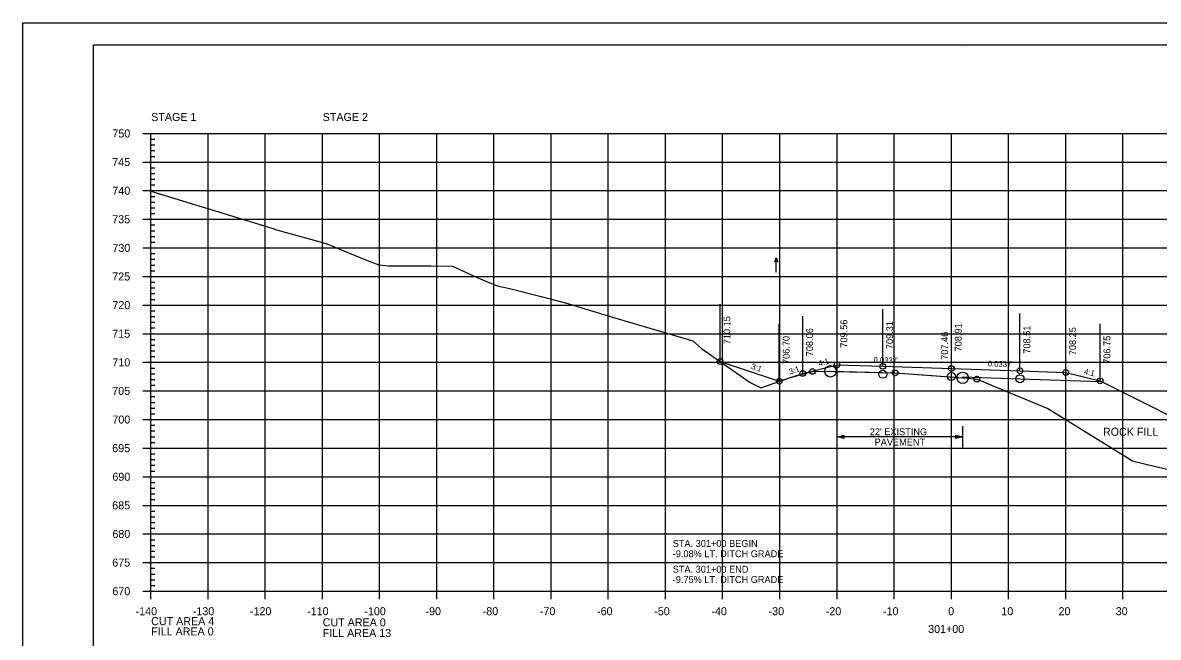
# Model space of a CAD drawing. Extents: x 1370515 to 1370849, y 383299 to 386073.
# Drawn here: x 1370515.4 to 1370714, y 383618.7 to 383726.1 of the extents above; entities that cross this region are included whole.
import ezdxf

# ---------------------------------------------------------------- set-up
doc = ezdxf.new("R2010")
doc.units = 0
for name, color, linetype in [('R_Alt Surface', 7, 'Continuous'), ('R_Axis', 7, 'Continuous'), ('R_Axis Annot', 7, 'Continuous'), ('R_Border', 7, 'Continuous'), ('R_Drive', 7, 'Continuous'), ('R_Exist Surface', 7, 'Continuous'), ('R_Fin Surface', 7, 'Continuous'), ('R_Grid', 7, 'Continuous'), ('R_No Plot', 7, 'Continuous'), ('R_ROW Annot', 7, 'Continuous'), ('R_Water Annot', 7, 'Continuous'), ('R_Xsect Elev', 7, 'Continuous'), ('R_Xsect Slope', 7, 'Continuous')]:
    doc.layers.add(name, color=color, linetype=linetype)

msp = doc.modelspace()

# ---------------------------------------------------------------- linework, layer by layer
at = {"layer": 'R_Alt Surface'}
msp.add_lwpolyline([(1370653.2, 383665.16), (1370656.65, 383665.18), (1370667.97, 383664.9), (1370679.78, 383664.05), (1370679.78, 383664.21), (1370689.8, 383663.88), (1370703.96, 383663.41)], dxfattribs=at)
at = {"layer": 'R_Axis'}
for p, q in [((1370536.4, 383706.75), (1370539.2, 383706.75)), ((1370537.8, 383626.75), (1370537.8, 383706.75)), ((1370537.8, 383705.75), (1370538.5, 383705.75)), ((1370537.8, 383704.75), (1370538.5, 383704.75)), ((1370537.8, 383703.75), (1370538.5, 383703.75)), ((1370536.4, 383701.75), (1370539.2, 383701.75)), ((1370537.8, 383702.75), (1370538.5, 383702.75)), ((1370537.8, 383700.75), (1370538.5, 383700.75)), ((1370537.8, 383699.75), (1370538.5, 383699.75)), ((1370537.8, 383698.75), (1370538.5, 383698.75)), ((1370537.8, 383697.75), (1370538.5, 383697.75)), ((1370536.4, 383696.75), (1370539.2, 383696.75)), ((1370537.8, 383695.75), (1370538.5, 383695.75)), ((1370537.8, 383694.75), (1370538.5, 383694.75)), ((1370537.8, 383693.75), (1370538.5, 383693.75)), ((1370536.4, 383691.75), (1370539.2, 383691.75)), ((1370537.8, 383692.75), (1370538.5, 383692.75)), ((1370537.8, 383690.75), (1370538.5, 383690.75)), ((1370537.8, 383689.75), (1370538.5, 383689.75)), ((1370537.8, 383688.75), (1370538.5, 383688.75)), ((1370537.8, 383687.75), (1370538.5, 383687.75)), ((1370536.4, 383686.75), (1370539.2, 383686.75)), ((1370537.8, 383685.75), (1370538.5, 383685.75)), ((1370537.8, 383684.75), (1370538.5, 383684.75)), ((1370537.8, 383683.75), (1370538.5, 383683.75)), ((1370536.4, 383681.75), (1370539.2, 383681.75)), ((1370537.8, 383682.75), (1370538.5, 383682.75)), ((1370537.8, 383680.75), (1370538.5, 383680.75)), ((1370537.8, 383679.75), (1370538.5, 383679.75)), ((1370537.8, 383678.75), (1370538.5, 383678.75)), ((1370537.8, 383677.75), (1370538.5, 383677.75)), ((1370536.4, 383676.75), (1370539.2, 383676.75)), ((1370537.8, 383675.75), (1370538.5, 383675.75)), ((1370537.8, 383674.75), (1370538.5, 383674.75)), ((1370537.8, 383673.75), (1370538.5, 383673.75)), ((1370536.4, 383671.75), (1370539.2, 383671.75)), ((1370537.8, 383672.75), (1370538.5, 383672.75)), ((1370537.8, 383670.75), (1370538.5, 383670.75)), ((1370537.8, 383669.75), (1370538.5, 383669.75)), ((1370537.8, 383668.75), (1370538.5, 383668.75)), ((1370537.8, 383667.75), (1370538.5, 383667.75)), ((1370536.4, 383666.75), (1370539.2, 383666.75)), ((1370537.8, 383665.75), (1370538.5, 383665.75)), ((1370537.8, 383664.75), (1370538.5, 383664.75)), ((1370537.8, 383663.75), (1370538.5, 383663.75)), ((1370536.4, 383661.75), (1370539.2, 383661.75)), ((1370537.8, 383662.75), (1370538.5, 383662.75)), ((1370537.8, 383660.75), (1370538.5, 383660.75)), ((1370537.8, 383659.75), (1370538.5, 383659.75)), ((1370537.8, 383658.75), (1370538.5, 383658.75)), ((1370537.8, 383657.75), (1370538.5, 383657.75)), ((1370536.4, 383656.75), (1370539.2, 383656.75)), ((1370537.8, 383655.75), (1370538.5, 383655.75)), ((1370537.8, 383654.75), (1370538.5, 383654.75)), ((1370537.8, 383653.75), (1370538.5, 383653.75)), ((1370536.4, 383651.75), (1370539.2, 383651.75)), ((1370537.8, 383652.75), (1370538.5, 383652.75)), ((1370537.8, 383650.75), (1370538.5, 383650.75)), ((1370537.8, 383649.75), (1370538.5, 383649.75)), ((1370537.8, 383648.75), (1370538.5, 383648.75)), ((1370537.8, 383647.75), (1370538.5, 383647.75)), ((1370536.4, 383646.75), (1370539.2, 383646.75)), ((1370537.8, 383645.75), (1370538.5, 383645.75)), ((1370537.8, 383644.75), (1370538.5, 383644.75)), ((1370537.8, 383643.75), (1370538.5, 383643.75)), ((1370536.4, 383641.75), (1370539.2, 383641.75)), ((1370537.8, 383642.75), (1370538.5, 383642.75)), ((1370537.8, 383640.75), (1370538.5, 383640.75)), ((1370537.8, 383639.75), (1370538.5, 383639.75)), ((1370537.8, 383638.75), (1370538.5, 383638.75)), ((1370537.8, 383637.75), (1370538.5, 383637.75)), ((1370536.4, 383636.75), (1370539.2, 383636.75)), ((1370537.8, 383635.75), (1370538.5, 383635.75)), ((1370537.8, 383634.75), (1370538.5, 383634.75)), ((1370537.8, 383633.75), (1370538.5, 383633.75)), ((1370536.4, 383631.75), (1370539.2, 383631.75)), ((1370537.8, 383632.75), (1370538.5, 383632.75)), ((1370537.8, 383630.75), (1370538.5, 383630.75)), ((1370537.8, 383629.75), (1370538.5, 383629.75)), ((1370537.8, 383628.75), (1370538.5, 383628.75)), ((1370537.8, 383625.35), (1370537.8, 383628.15)), ((1370537.8, 383627.75), (1370538.5, 383627.75)), ((1370547.8, 383625.35), (1370547.8, 383628.15)), ((1370557.8, 383625.35), (1370557.8, 383628.15)), ((1370567.8, 383625.35), (1370567.8, 383628.15)), ((1370577.8, 383625.35), (1370577.8, 383628.15)), ((1370587.8, 383625.35), (1370587.8, 383628.15)), ((1370597.8, 383625.35), (1370597.8, 383628.15)), ((1370607.8, 383625.35), (1370607.8, 383628.15)), ((1370617.8, 383625.35), (1370617.8, 383628.15)), ((1370627.8, 383625.35), (1370627.8, 383628.15)), ((1370637.8, 383625.35), (1370637.8, 383628.15)), ((1370647.8, 383625.35), (1370647.8, 383628.15)), ((1370657.8, 383625.35), (1370657.8, 383628.15)), ((1370667.8, 383625.35), (1370667.8, 383628.15)), ((1370677.8, 383625.35), (1370677.8, 383628.15)), ((1370687.8, 383625.35), (1370687.8, 383628.15)), ((1370697.8, 383625.35), (1370697.8, 383628.15)), ((1370707.8, 383625.35), (1370707.8, 383628.15)), ((1370536.4, 383626.75), (1370539.2, 383626.75)), ((1370537.8, 383626.75), (1370817.8, 383626.75))]:
    msp.add_line(p, q, dxfattribs=at)
at = {"layer": 'R_Border'}
for p, q in [((1370527.8, 383722.21), (1370843.98, 383722.21)), ((1370527.8, 383516.75), (1370527.8, 383722.21)), ((1370680.32, 383721.95), (1370680.32, 383721.95)), ((1370680.32, 383721.95), (1370680.32, 383721.95))]:
    msp.add_line(p, q, dxfattribs=at)
at = {"layer": 'R_Exist Surface'}
msp.add_lwpolyline([(1370537.8, 383696.68), (1370559.38, 383690.06), (1370559.45, 383690.03), (1370559.79, 383689.93), (1370567.41, 383687.8), (1370568.57, 383687.48), (1370575.54, 383684.63), (1370577.66, 383683.77), (1370578.88, 383683.67), (1370579.39, 383683.62), (1370586.76, 383683.6), (1370590.58, 383683.55), (1370594.99, 383681.51), (1370598.39, 383680.09), (1370600.31, 383679.69), (1370606.05, 383678.23), (1370610.31, 383677.15), (1370618.56, 383674.66), (1370632.56, 383670.53), (1370634.12, 383669.14), (1370642.61, 383663.25), (1370644.47, 383662.29), (1370649.68, 383664.07), (1370650.39, 383664.28), (1370653.42, 383665.13), (1370653.51, 383665.16), (1370656.63, 383665.18), (1370656.65, 383665.18), (1370657.29, 383665.16), (1370667.97, 383664.9), (1370678.41, 383664.16), (1370679.78, 383664.05), (1370680.07, 383664.03), (1370682.27, 383663.82), (1370682.6, 383663.68), (1370684.1, 383663.04), (1370693.65, 383659.08), (1370694.69, 383658.65), (1370708.06, 383650.39), (1370709.49, 383649.54), (1370711.57, 383649.01), (1370723.09, 383646.26)], dxfattribs=at)
at = {"layer": 'R_Fin Surface'}
msp.add_lwpolyline([(1370637.35, 383666.9), (1370647.71, 383663.45), (1370651.8, 383664.81), (1370657.8, 383666.31), (1370665.8, 383666.05), (1370677.8, 383665.65), (1370689.8, 383665.26), (1370697.8, 383664.99), (1370703.8, 383663.49), (1370744.75, 383643.02), (1370751.75, 383643.02), (1370755.24, 383644.18)], dxfattribs=at)
at = {"layer": 'R_Grid'}
for p, q in [((1370537.8, 383706.75), (1370817.8, 383706.75)), ((1370537.8, 383626.75), (1370537.8, 383706.75)), ((1370547.8, 383626.75), (1370547.8, 383706.75)), ((1370557.8, 383626.75), (1370557.8, 383706.75)), ((1370567.8, 383626.75), (1370567.8, 383706.75)), ((1370577.8, 383626.75), (1370577.8, 383706.75)), ((1370587.8, 383626.75), (1370587.8, 383706.75)), ((1370597.8, 383626.75), (1370597.8, 383706.75)), ((1370607.8, 383626.75), (1370607.8, 383706.75)), ((1370617.8, 383626.75), (1370617.8, 383706.75)), ((1370627.8, 383626.75), (1370627.8, 383706.75)), ((1370637.8, 383626.75), (1370637.8, 383706.75)), ((1370647.8, 383626.75), (1370647.8, 383706.75)), ((1370657.8, 383626.75), (1370657.8, 383706.75)), ((1370667.8, 383626.75), (1370667.8, 383706.75)), ((1370677.8, 383626.75), (1370677.8, 383706.75)), ((1370687.8, 383626.75), (1370687.8, 383706.75)), ((1370697.8, 383626.75), (1370697.8, 383706.75)), ((1370707.8, 383626.75), (1370707.8, 383706.75)), ((1370537.8, 383701.75), (1370817.8, 383701.75)), ((1370537.8, 383696.75), (1370817.8, 383696.75)), ((1370537.8, 383691.75), (1370817.8, 383691.75)), ((1370537.8, 383686.75), (1370817.8, 383686.75)), ((1370537.8, 383681.75), (1370817.8, 383681.75)), ((1370537.8, 383676.75), (1370817.8, 383676.75)), ((1370537.8, 383671.75), (1370817.8, 383671.75)), ((1370537.8, 383666.75), (1370817.8, 383666.75)), ((1370537.8, 383661.75), (1370817.8, 383661.75)), ((1370537.8, 383656.75), (1370817.8, 383656.75)), ((1370537.8, 383651.75), (1370817.8, 383651.75)), ((1370537.8, 383646.75), (1370817.8, 383646.75)), ((1370537.8, 383641.75), (1370817.8, 383641.75)), ((1370537.8, 383636.75), (1370817.8, 383636.75)), ((1370537.8, 383631.75), (1370817.8, 383631.75)), ((1370537.8, 383626.75), (1370817.8, 383626.75))]:
    msp.add_line(p, q, dxfattribs=at)
at = {"layer": 'R_No Plot'}
msp.add_line((1370515.4, 383726.1), (1370848.73, 383726.1), dxfattribs=at)
for points in [[(1370515.39, 383726.1), (1370848.73, 383726.1), (1370848.73, 383512.76), (1370515.39, 383512.76)], [(1370761.72, 383722.21), (1370761.72, 383712.33), (1370797.45, 383712.33), (1370797.45, 383709.41), (1370820.65, 383709.41), (1370820.65, 383686.19), (1370843.98, 383686.19), (1370843.98, 383516.75), (1370527.8, 383516.75), (1370527.8, 383722.21)]]:
    msp.add_lwpolyline(points, close=True, dxfattribs=at)
for centre, radius in [((1370637.35, 383666.9), 0.5), ((1370653.51, 383665.16), 0.5), ((1370656.65, 383665.18), 1), ((1370657.8, 383666.31), 0.5), ((1370665.8, 383664.67), 0.7), ((1370665.8, 383666.05), 0.5), ((1370667.97, 383664.9), 0.5), ((1370677.8, 383665.65), 0.5), ((1370689.8, 383665.26), 0.5), ((1370697.8, 383664.99), 0.5), ((1370647.71, 383663.45), 0.5), ((1370651.8, 383664.81), 0.5), ((1370651.8, 383664.81), 0.5), ((1370677.8, 383664.28), 0.7), ((1370677.8, 383664.28), 0.7), ((1370679.78, 383664.05), 1), ((1370682.27, 383663.82), 0.5), ((1370689.8, 383663.88), 0.7), ((1370703.8, 383663.49), 0.5), ((1370703.8, 383663.49), 0.5)]:
    msp.add_circle(centre, radius, dxfattribs=at)
at = {"layer": 'R_ROW Annot'}
for p, q in [((1370657.8, 383651.83), (1370657.8, 383655.6)), ((1370679.8, 383651.83), (1370679.8, 383655.6)), ((1370679.8, 383653.71), (1370657.8, 383653.71))]:
    msp.add_line(p, q, dxfattribs=at)
for points in [[(1370659, 383653.41), (1370657.8, 383653.71), (1370659, 383654.01)], [(1370678.6, 383654.01), (1370679.8, 383653.71), (1370678.6, 383653.41)]]:
    msp.add_lwpolyline(points, close=True, dxfattribs=at)
at = {"layer": 'R_Water Annot'}
for p, q in [((1370647.15, 383685.04), (1370646.87, 383684.27)), ((1370647.15, 383682.52), (1370647.15, 383685.04)), ((1370647.15, 383685.04), (1370647.43, 383684.27))]:
    msp.add_line(p, q, dxfattribs=at)
at = {"layer": 'R_Xsect Elev'}
for p, q in [((1370637.35, 383666.9), (1370637.35, 383676.9)), ((1370657.8, 383666.31), (1370657.8, 383676.31)), ((1370665.8, 383666.05), (1370665.8, 383676.05)), ((1370677.8, 383665.65), (1370677.8, 383675.65)), ((1370647.71, 383663.45), (1370647.71, 383673.45)), ((1370651.8, 383664.81), (1370651.8, 383674.81)), ((1370677.82, 383664.19), (1370677.82, 383674.19)), ((1370689.8, 383665.26), (1370689.8, 383675.26)), ((1370697.8, 383664.99), (1370697.8, 383674.99)), ((1370703.8, 383663.49), (1370703.8, 383673.49))]:
    msp.add_line(p, q, dxfattribs=at)

# ---------------------------------------------------------------- texts
at = {"layer": 'R_Axis'}
msp.add_text('-', height=0.0001, dxfattribs=at).set_placement((1370537.8, 383626.75))
at = {"layer": 'R_Axis Annot'}
for s, p in [('STAGE 1', (1370537.86, 383708.93)), ('STAGE 2', (1370567.86, 383708.93)), ('750', (1370531.08, 383706.05)), ('745', (1370531.05, 383701.05)), ('740', (1370531.08, 383696.05)), ('735', (1370531.05, 383691.05)), ('730', (1370531.08, 383686.05)), ('725', (1370531.05, 383681.05)), ('720', (1370531.08, 383676.05)), ('715', (1370531.05, 383671.05)), ('710', (1370531.08, 383666.05)), ('705', (1370531.05, 383661.05)), ('700', (1370531.08, 383656.05)), ('ROCK FILL', (1370704.31, 383653.91)), ('695', (1370531.05, 383651.05)), ('690', (1370531.08, 383646.05)), ('685', (1370531.05, 383641.05)), ('680', (1370531.08, 383636.05)), ('675', (1370531.05, 383631.05)), ('670', (1370531.08, 383626.05)), ('-140', (1370535.14, 383622.55)), ('-130', (1370545.14, 383622.55)), ('-120', (1370555.14, 383622.55)), ('-110', (1370565.14, 383622.55)), ('-100', (1370575.14, 383622.55)), ('-90', (1370585.84, 383622.55)), ('-80', (1370595.84, 383622.55)), ('-70', (1370605.84, 383622.55)), ('-60', (1370615.84, 383622.55)), ('-50', (1370625.84, 383622.55)), ('-40', (1370635.84, 383622.55)), ('-30', (1370645.84, 383622.55)), ('-20', (1370655.84, 383622.55)), ('-10', (1370665.84, 383622.55)), ('0', (1370677.24, 383622.55)), ('10', (1370686.54, 383622.55)), ('20', (1370696.54, 383622.55)), ('30', (1370706.54, 383622.55)), ('CUT AREA 4', (1370537.86, 383620.81)), ('CUT AREA 0', (1370567.86, 383620.61)), ('FILL AREA 0', (1370537.86, 383619.02)), ('FILL AREA 13', (1370567.86, 383618.75)), ('301+00', (1370673.74, 383619.45))]:
    msp.add_text(s, height=1.4, dxfattribs=at).set_placement(p)
at = {"layer": 'R_Drive'}
for s, p in [('STA. 301+00 BEGIN', (1370629.07, 383634.49)), ('-9.08% LT. DITCH GRADE', (1370629.07, 383632.69)), ('STA. 301+00 END', (1370629.07, 383629.99)), ('-9.75% LT. DITCH GRADE', (1370629.07, 383628.19))]:
    msp.add_text(s, height=1.2, dxfattribs=at).set_placement(p)
at = {"layer": 'R_No Plot'}
for p in [(1370568.53, 383687.43), (1370577.62, 383683.72), (1370579.35, 383683.57), (1370590.54, 383683.5), (1370598.35, 383680.04), (1370610.27, 383677.1), (1370632.52, 383670.48), (1370650.34, 383664.23), (1370644.42, 383662.24), (1370684.06, 383662.99), (1370694.64, 383658.6), (1370709.45, 383649.49)]:
    msp.add_text('+', height=0.1, dxfattribs=at).set_placement(p)
at = {"layer": 'R_ROW Annot'}
for s, p in [("22' EXISTING", (1370663.53, 383654.01)), ('PAVEMENT', (1370664.38, 383652.21))]:
    msp.add_text(s, height=1.2, dxfattribs=at).set_placement(p)
at = {"layer": 'R_Xsect Elev'}
for s, p in [('710.15', (1370639.15, 383669.9)), ('709.56', (1370659.6, 383669.31)), ('709.31', (1370667.6, 383669.05)), ('708.91', (1370679.6, 383668.65)), ('708.06', (1370653.6, 383667.81)), ('707.46', (1370677.22, 383667.19)), ('708.51', (1370691.6, 383668.26)), ('708.25', (1370699.6, 383667.99)), ('706.75', (1370705.6, 383666.49)), ('706.70', (1370649.51, 383666.45))]:
    msp.add_text(s, height=1.2, rotation=90, dxfattribs=at).set_placement(p)
at = {"layer": 'R_Xsect Slope'}
for s, rotation, p in [('4:1', 14.0362, (1370654.68, 383666.04)), ("0.033'/'", 358.1156, (1370664.17, 383666.7)), ('3:1', 341.5651, (1370642.69, 383665.65)), ('3:1', 18.4349, (1370649.6, 383664.6)), ("0.033'/'", 358.1156, (1370684.17, 383666.04)), ('4:1', 345.9638, (1370700.92, 383664.73))]:
    msp.add_text(s, height=1, rotation=rotation, dxfattribs=at).set_placement(p)

doc.saveas('drawing.dxf')
